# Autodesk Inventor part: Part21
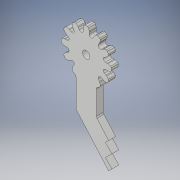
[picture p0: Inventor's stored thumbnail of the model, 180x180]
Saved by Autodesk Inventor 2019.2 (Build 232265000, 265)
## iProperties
Created: 2019-04
Part Number: Part21
Material: Generic
Document SubType Name: Modeling
Designer: richard.girt
Mass: 1.20236 g
Surface Area: 13.08 cm^2
Volume: 1.20236 cm^3
Density: 1 g/cm^3
Appearance: Default
Author: richard.girt
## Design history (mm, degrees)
sketch "Sketch1"
  geometry: L1 (10.319, -34.606)-(9, -35.924); L2 (9, -35.924)-(-3.822, -21.298); L3 (-4.07, -20.638)-(-4.07, -9.868); L4 (4.07, -9.868)-(4.07, -19.332); L5 (4.318, -19.991)-(9, -25.375); L6 (9, -25.375)-(7.681, -26.694); L7 (7.681, -26.694)-(10.319, -29.331); L8 (10.319, -29.331)-(7.681, -31.968); L9 (7.681, -31.968)-(10.319, -34.606); L10 (-1.234, 8.418)-(-1.234, 7.677); L11 (1.234, 8.418)-(1.234, 7.677); L12 (-0.435, 10.081)-(0.435, 10.081); L13 (-5.278, 6.673)-(-4.907, 6.032); L14 (-3.14, 7.907)-(-2.77, 7.266); L15 (-5.417, 8.513)-(-4.663, 8.948); L16 (-7.907, 3.14)-(-7.266, 2.77); L17 (-6.673, 5.278)-(-6.032, 4.907); L18 (-8.948, 4.663)-(-8.513, 5.417); L19 (-8.418, -1.234)-(-7.677, -1.234); L20 (-8.418, 1.234)-(-7.677, 1.234); L21 (-10.081, -0.435)-(-10.081, 0.435); L22 (-6.673, -5.278)-(-6.032, -4.907); L23 (-7.907, -3.14)-(-7.266, -2.77); L24 (-8.513, -5.417)-(-8.948, -4.663); L25 (-5.278, -6.673)-(-4.907, -6.032); L26 (-4.57, -9.002)-(-5.417, -8.513); L27 (5.278, -6.673)-(4.907, -6.032); L28 (5.417, -8.513)-(4.57, -9.002); L29 (7.907, -3.14)-(7.266, -2.77); L30 (6.673, -5.278)-(6.032, -4.907); L31 (8.948, -4.663)-(8.513, -5.417); L32 (8.418, 1.234)-(7.677, 1.234); L33 (8.418, -1.234)-(7.677, -1.234); L34 (10.081, 0.435)-(10.081, -0.435); L35 (6.673, 5.278)-(6.032, 4.907); L36 (7.907, 3.14)-(7.266, 2.77); L37 (8.513, 5.417)-(8.948, 4.663); L38 (3.14, 7.907)-(2.77, 7.266); L39 (5.278, 6.673)-(4.907, 6.032); L40 (4.663, 8.948)-(5.417, 8.513); C1 r 1.5 at (0, 0); A1 r 1 centre (-3.07, -20.638) between (-4.07, -20.638) and (-3.822, -21.298); A2 r 1 centre (5.07, -19.332) between (4.07, -19.332) and (4.318, -19.991); A3 r 3.65 centre (2.389, 8.132) between (-0.882, 9.749) and (-1.207, 8.751); A4 r 0.5 centre (-0.411, 9.581) between (-0.435, 10.081) and (-0.882, 9.749); A5 r 2.094 centre (0.86, 8.418) between (-1.188, 8.854) and (-1.234, 8.418); A6 r 0.823 centre (-2.057, 7.677) between (-1.844, 6.882) and (-1.234, 7.677); A7 r 3.65 centre (-2.389, 8.132) between (1.207, 8.751) and (0.882, 9.749); A8 r 0.5 centre (0.411, 9.581) between (0.882, 9.749) and (0.435, 10.081); A9 r 2.094 centre (-0.86, 8.418) between (1.234, 8.418) and (1.207, 8.751); A10 r 0.823 centre (2.057, 7.677) between (1.234, 7.677) and (1.844, 6.882); A11 r 3.65 centre (-1.997, 8.237) between (-5.639, 8.002) and (-5.456, 7.074); A12 r 0.5 centre (-5.147, 8.092) between (-5.417, 8.513) and (-5.639, 8.002); A13 r 2.094 centre (-3.464, 7.72) between (-5.456, 7.074) and (-5.278, 6.673); A14 r 0.823 centre (-5.62, 5.62) between (-5.038, 5.038) and (-4.907, 6.032); A15 r 3.65 centre (-6.135, 5.848) between (-3.33, 8.183) and (-4.111, 8.884); A16 r 0.5 centre (-4.434, 8.503) between (-4.111, 8.884) and (-4.663, 8.948); A17 r 2.094 centre (-4.953, 6.86) between (-3.14, 7.907) and (-3.398, 8.262); A18 r 0.823 centre (-2.057, 7.677) between (-2.77, 7.266) and (-1.844, 6.882); A19 r 3.65 centre (-5.848, 6.135) between (-8.884, 4.111) and (-8.262, 3.398); A20 r 0.5 centre (-8.503, 4.434) between (-8.948, 4.663) and (-8.884, 4.111); A21 r 2.094 centre (-6.86, 4.953) between (-8.262, 3.398) and (-7.907, 3.14); A22 r 0.823 centre (-7.677, 2.057) between (-6.882, 1.844) and (-7.266, 2.77); A23 r 3.65 centre (-8.237, 1.997) between (-6.975, 5.421) and (-8.002, 5.639); A24 r 0.5 centre (-8.092, 5.147) between (-8.002, 5.639) and (-8.513, 5.417); A25 r 2.094 centre (-7.72, 3.464) between (-6.673, 5.278) and (-7.074, 5.456); A26 r 0.823 centre (-5.62, 5.62) between (-6.032, 4.907) and (-5.038, 5.038); A27 r 3.65 centre (-8.132, 2.389) between (-9.749, -0.882) and (-8.854, -1.188); A28 r 0.5 centre (-9.581, -0.411) between (-10.081, -0.435) and (-9.749, -0.882); A29 r 2.094 centre (-8.418, 0.86) between (-8.854, -1.188) and (-8.418, -1.234); A30 r 0.823 centre (-7.677, -2.057) between (-6.882, -1.844) and (-7.677, -1.234); A31 r 3.65 centre (-8.132, -2.389) between (-8.751, 1.207) and (-9.749, 0.882); A32 r 0.5 centre (-9.581, 0.411) between (-9.749, 0.882) and (-10.081, 0.435); A33 r 2.094 centre (-8.418, -0.86) between (-8.418, 1.234) and (-8.751, 1.207); A34 r 0.823 centre (-7.677, 2.057) between (-7.677, 1.234) and (-6.882, 1.844); A35 r 3.65 centre (-8.237, -1.997) between (-8.002, -5.639) and (-6.975, -5.421); A36 r 0.5 centre (-8.092, -5.147) between (-8.513, -5.417) and (-8.002, -5.639); A37 r 2.094 centre (-7.72, -3.464) between (-7.074, -5.456) and (-6.673, -5.278); A38 r 0.823 centre (-5.62, -5.62) between (-5.038, -5.038) and (-6.032, -4.907); A39 r 3.65 centre (-5.848, -6.135) between (-8.183, -3.33) and (-8.884, -4.111); A40 r 0.5 centre (-8.503, -4.434) between (-8.884, -4.111) and (-8.948, -4.663); A41 r 2.094 centre (-6.86, -4.953) between (-7.907, -3.14) and (-8.183, -3.33); A42 r 0.823 centre (-7.677, -2.057) between (-7.266, -2.77) and (-6.882, -1.844); A43 r 3.65 centre (-1.997, -8.237) between (-5.421, -6.975) and (-5.639, -8.002); A44 r 0.5 centre (-5.147, -8.092) between (-5.639, -8.002) and (-5.417, -8.513); A45 r 2.094 centre (-3.464, -7.72) between (-5.278, -6.673) and (-5.421, -6.975); A46 r 0.823 centre (-5.62, -5.62) between (-4.907, -6.032) and (-5.038, -5.038); A47 r 1 centre (-5.07, -9.868) between (-4.07, -9.868) and (-4.57, -9.002); A48 r 3.65 centre (1.997, -8.237) between (5.639, -8.002) and (5.421, -6.975); A49 r 0.5 centre (5.147, -8.092) between (5.417, -8.513) and (5.639, -8.002); A50 r 2.094 centre (3.464, -7.72) between (5.421, -6.975) and (5.278, -6.673); A51 r 0.823 centre (5.62, -5.62) between (5.038, -5.038) and (4.907, -6.032); A52 r 1 centre (5.07, -9.868) between (4.57, -9.002) and (4.07, -9.868); A53 r 3.65 centre (5.848, -6.135) between (8.884, -4.111) and (8.183, -3.33); A54 r 0.5 centre (8.503, -4.434) between (8.948, -4.663) and (8.884, -4.111); A55 r 2.094 centre (6.86, -4.953) between (8.183, -3.33) and (7.907, -3.14); A56 r 0.823 centre (7.677, -2.057) between (6.882, -1.844) and (7.266, -2.77); A57 r 3.65 centre (8.237, -1.997) between (7.074, -5.456) and (8.002, -5.639); A58 r 0.5 centre (8.092, -5.147) between (8.002, -5.639) and (8.513, -5.417); A59 r 2.094 centre (7.72, -3.464) between (6.673, -5.278) and (7.074, -5.456); A60 r 0.823 centre (5.62, -5.62) between (6.032, -4.907) and (5.038, -5.038); A61 r 3.65 centre (8.132, -2.389) between (9.749, 0.882) and (8.751, 1.207); A62 r 0.5 centre (9.581, 0.411) between (10.081, 0.435) and (9.749, 0.882); A63 r 2.094 centre (8.418, -0.86) between (8.751, 1.207) and (8.418, 1.234); A64 r 0.823 centre (7.677, 2.057) between (6.882, 1.844) and (7.677, 1.234)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; 1 further point
  constraints: 208 point on circle, 85 centre point, 80 end point
  dimensions: "d0" = 3 diameter of C1
extrude "Extrusion1" new body sketch "Sketch1" stored distance "d1" = 2.8; taper "d2" = 0 deg
extrude "Extrusion2" cut sketch "Sketch1" extent not by distance; stored distance "d3" = 2.8; taper "d4" = 0 deg
body "Solid1"
